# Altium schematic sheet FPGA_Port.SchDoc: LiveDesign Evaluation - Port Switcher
size A4; Organization: Altium Limited; Address1: L3, 12a Rodborough Rd; Address2: Frenchs Forest; Address3: NSW; Address4: Australia 2086
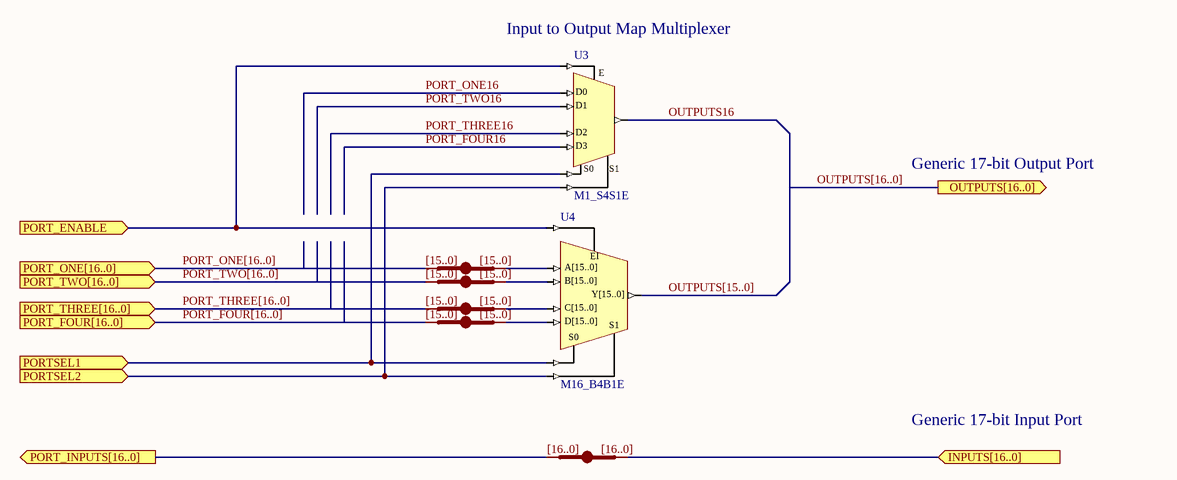
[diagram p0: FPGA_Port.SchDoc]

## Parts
JB_S1  IndexA: [16..0]  (hidden comment: JB)
JB_S2  IndexA: [15..0]  (hidden comment: JB)
JB_S3  IndexA: [15..0]  (hidden comment: JB)
JB_S4  IndexA: [15..0]  (hidden comment: JB)
JB_S5  IndexA: [15..0]  (hidden comment: JB)
U3  M1_S4S1E
U4  M16_B4B1E

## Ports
INPUTS[16..0] (in), OUTPUTS[16..0] (out), PORT_ENABLE (in), PORT_FOUR[16..0] (in), PORT_INPUTS[16..0] (out), PORT_ONE[16..0] (in), PORT_THREE[16..0] (in), PORT_TWO[16..0] (in), PORTSEL1 (in), PORTSEL2 (in)

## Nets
OUTPUTS16: U3.O
PORT_ENABLE: U3.E U4.EI ; port PORT_ENABLE
PORT_FOUR16: U3.D3
PORT_ONE16: U3.D0
PORT_THREE16: U3.D2
PORT_TWO16: U3.D1
PORTSEL1: U3.S0 U4.S0 ; port PORTSEL1
PORTSEL2: U3.S1 U4.S1 ; port PORTSEL2

Not connected (* = marked no-connect by the designer): JB_S1 A[0..0] B[0..0]; JB_S2 A[0..0] B[0..0]; JB_S3 A[0..0] B[0..0]; JB_S4 A[0..0] B[0..0]; JB_S5 A[0..0] B[0..0]; U4 A[15..0] B[15..0] C[15..0] D[15..0] Y[15..0]

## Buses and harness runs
bus OUTPUTS[15..0]
bus OUTPUTS[16..0] = port OUTPUTS[16..0]
bus PORT_FOUR[16..0] = port PORT_FOUR[16..0]
bus PORT_ONE[16..0] = port PORT_ONE[16..0]
bus PORT_THREE[16..0] = port PORT_THREE[16..0]
bus PORT_TWO[16..0] = port PORT_TWO[16..0]

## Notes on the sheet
- (near U3) Input to Output Map Multiplexer
- Generic 17-bit Output Port
- Generic 17-bit Input Port

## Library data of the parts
JB_S1-JB_S5 = JB: System BUS Joiner
U3 = M1_S4S1E: 4x1-Single Wire to 1x1-Single Wire Multiplexer With Enable; Xilinx Equivalent: M4_1E; ArchiveName: GENERIC; VHDLIB_SIM: GENERIC_LIB
U4 = M16_B4B1E: 4x16-Bit Bus to 1x16-Bit Bus Multiplexer With Enable; ArchiveName: GENERIC; VHDLIB_SIM: GENERIC_LIB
